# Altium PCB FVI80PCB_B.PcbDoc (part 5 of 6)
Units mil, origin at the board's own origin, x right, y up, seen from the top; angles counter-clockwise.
Board outline 3540 x 3115 mil, 12 copper layers (Top Layer, Int1(GND), Int2(Signal), Int3(GND), Int4(Signal), Int5 (GND&PW), Int6 (GND&PW), Int7(Signal), Int8(GND), Int9(Signal), Int10(GND), Bottom Layer), stack 77.136 mil thick; 488 components, 321 nets, 1809 pads, 882 vias.
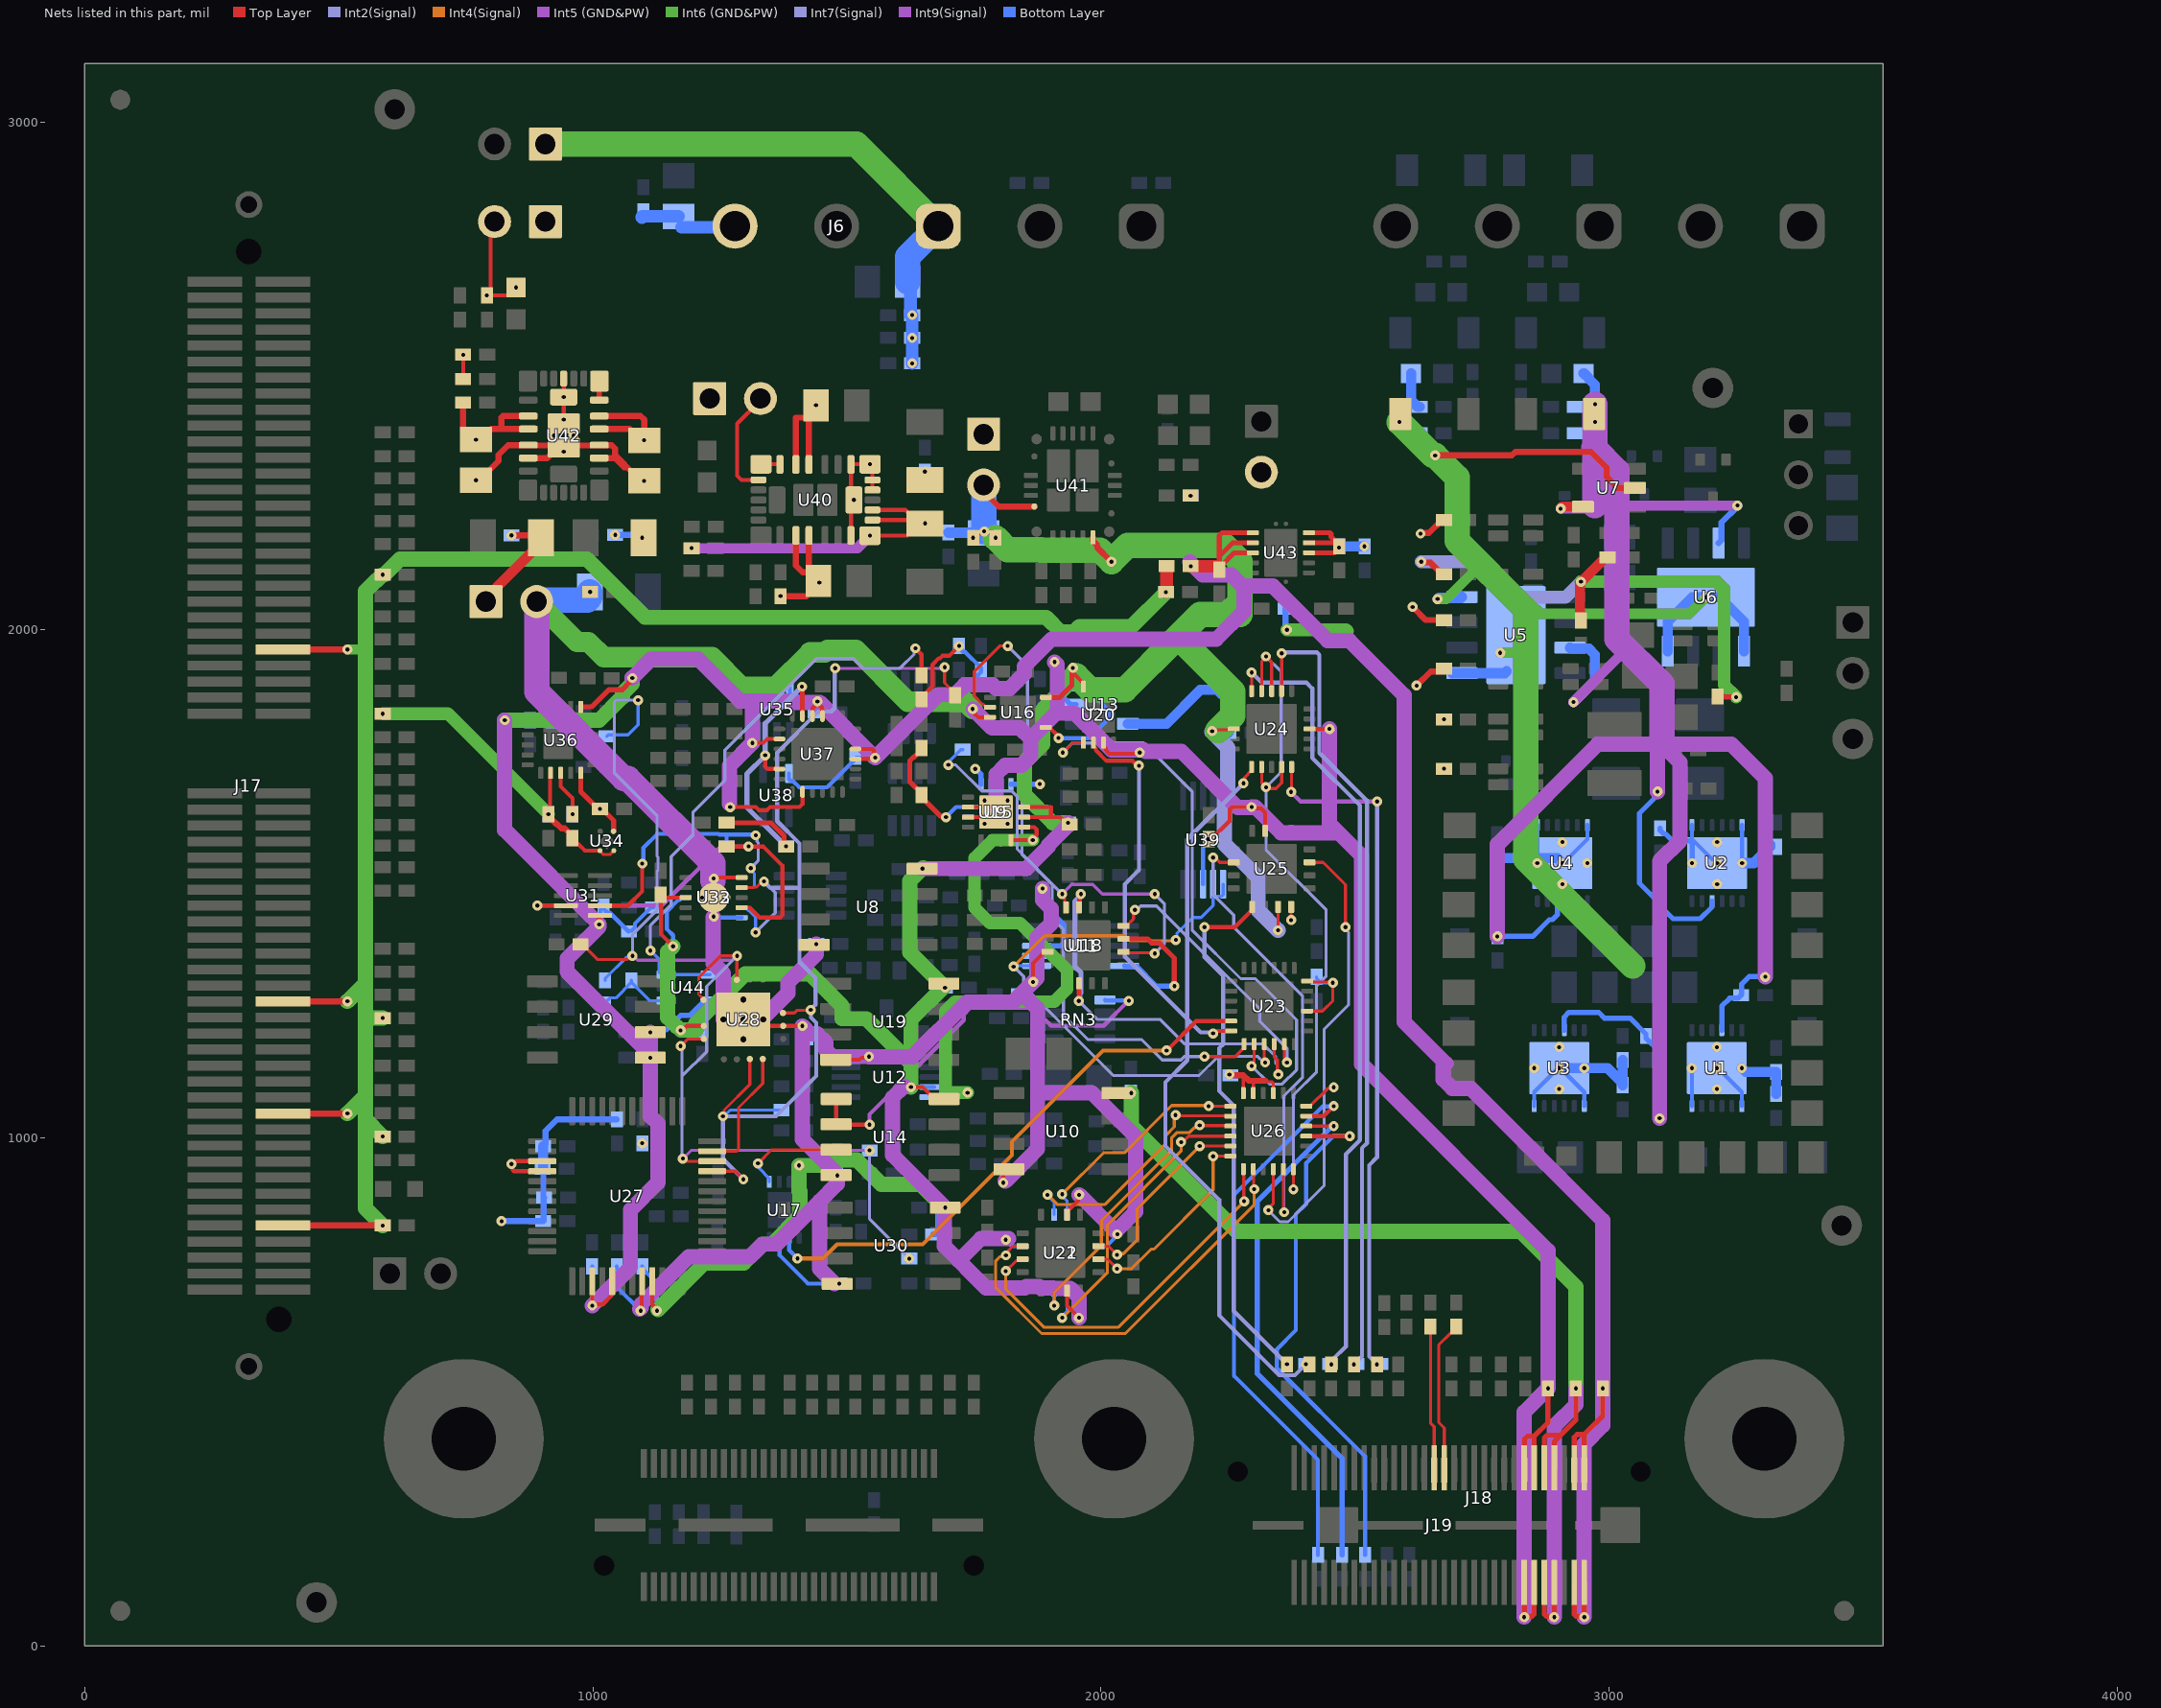
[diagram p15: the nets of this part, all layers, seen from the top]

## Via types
v1: diameter 19.68, hole 7.87, Top Layer to Bottom Layer, tented both sides, 834 vias
v2: diameter 19.68, hole 7.87, Top Layer to Bottom Layer, 39 vias
v3: diameter 23.62, hole 11.81, Top Layer to Bottom Layer, tented both sides, 5 vias
v4: diameter 19.68, hole 7.87, Top Layer to Bottom Layer, tented bottom, 4 vias

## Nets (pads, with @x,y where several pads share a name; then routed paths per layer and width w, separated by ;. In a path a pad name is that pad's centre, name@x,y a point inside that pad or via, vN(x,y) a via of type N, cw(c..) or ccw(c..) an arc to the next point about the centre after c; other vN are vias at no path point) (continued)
NetR200_1: R200.1 R204.1 U24.20 | length 1347.8
  Top Layer w6: v1(2374.57,1681.17) 2375.06,1681.66 2375.06,1729.89 U24.20@2375.56,1730.38
  Int2(Signal) w8: v1(2543.52,554.34) 2528,569.86 2528,946.38 2543.84,962.22 v1(2543.84,1662.52)
  Int9(Signal) w8: v1(2374.57,1681.17) 2393.22,1662.52 v1(2543.84,1662.52)
NetR201_2: R201.2 U26.15 | length 1060
  Top Layer w8: U26.15@2404.51,1003.71 2439.34,1003.71 2439.5,1003.55 2466.52,1003.55 2466.68,1003.71 v1(2489.73,1003.71)
  Bottom Layer w8: v1(2489.73,1003.71) 2489.57,1003.55 2457.07,1003.55 2404,950.48 2404,870 2384,850 2384,621.66 2346.5,584.16 2346.5,546.78 2520,373.28 R201.2@2520,179.27
NetR202_1: R202.1 R204.2 U24.7 | length 1597.6
  Top Layer w6: U24.7@2355.87,1879.99 v1(2355.87,1954)
  Int2(Signal) w8: v1(2355.87,1954) 2357.87,1956 2425.47,1956 2430.16,1951.31 2430.16,1757.89 2524,1664.05 2524,990.12 2514,980.12 2514,570.2 v1(2498.15,554.34)
NetR203_2: R203.2 U26.16 | length 1030.9
  Top Layer w6: U26.16@2404.51,1023.4 v1(2458.3,1023.4)
  Bottom Layer w10: v1(2458.3,1023.4) 2455.7,1023.4 2308,875.69 2308,536 2475,369 R203.2@2475,179.27
NetR205_1: R205.1 R208.1 U24.10 | length 1561.6
  Top Layer w6: U24.10@2296.82,1879.99 v1(2296.82,1916.36)
  Int2(Signal) w8: v1(2296.82,1916.36) 2316.66,1896.52 2404.64,1896.52 2416.16,1885 2416.16,1748.26 2510,1654.41 2510,995.92 2482.41,968.33 2482.41,589.62 2455.7,562.91 2455.7,556.58 v1(2453.46,554.34)
NetR206_2: R206.2 U26.17 | length 1107.5
  Top Layer w8: U26.17@2404.51,1043.08 2438.61,1043.08 v1(2458.3,1062.77)
  Bottom Layer w8: R206.2@2427.38,179.27 2427.38,366.62 2262.22,531.78 2262.22,887.84 2436.46,1062.07 2457.61,1062.07 v1(2458.3,1062.77)
NetR207_1: R207.1 R208.2 U24.16 | length 1422.3
  Top Layer w6: v1(2280.68,1698.42) 2283.3,1701.04 2283.3,1709.98 2296.82,1723.49 U24.16@2296.82,1730.38
  Int2(Signal) w8: v1(2280.68,1698.42) 2170,1587.74 2170,1152.75 2127.16,1109.91 2127.16,984.27 2233.01,878.43 2233.01,650.92 2350.93,533 2381.76,533 v1(2403.76,555)
NetR209_1: R209.1 U25.9 | length 1047.8
  Top Layer w8: v1(2203.87,1415.13) 2263.83,1415.13 2297.8,1449.1 U25.9@2297.8,1455.01
  Int2(Signal) w8: v1(2203.87,1415.13) 2203.87,1356.32 2240.84,1319.35 2240.84,1184.78 2233.06,1177 2233.06,1092.52 2261.38,1064.2 2261.38,659.96 v1(2366.34,555)
NetR232_2: R232.2 R234.1 U44.1 | length 158.9
  Bottom Layer w6: R232.2@1024.47,1262.96 1024.47,1266.89 1033.28,1275.7 1045.44,1275.7 R234.1@1076,1306.26 ; R234.1@1076,1310.2 R234.1@1076,1306.26 ; U44.1@1144.34,1270.41 1111.86,1270.41 R234.1@1076,1306.26
NetR233_1: R233.1 U44.3 U44.4 | length 1144.5
  Top Layer w8: v1(1635,1964) 1646.8,1952.2 R233.1@1646.8,1910.84
  Int2(Signal) w6: v1(1113.36,1368.84) 1113.36,1418.58 1154.24,1459.46 1154.24,1553.9 1197.35,1597.01 1197.35,1641.59 1259.97,1704.21 1259.97,1763.37 1440.44,1943.84 1512.93,1943.84 1532.16,1924.62 1604.65,1924.62 1632.38,1952.35 1632.38,1961.38 v1(1635,1964)
  Bottom Layer w6: v1(1113.36,1368.84) 1130.6,1351.6 1130.6,1326.47 1135.48,1321.59 U44.4@1230.95,1321.59
NetRN3_1: RN3.1 U14.1 U14.2 | length 822.7
  Top Layer w8: U14.1@1478.95,1076.72 U14.2@1478.95,1026.72 1479.24,1026.43 1544.53,1026.43 v1(1544.81,1026.14)
  Int9(Signal) w8: v1(1544.81,1026.14) 1544.81,1046.68 1730.16,1232.02 1730.16,1243.22 1742.99,1256.05 1862.62,1256.05 1886.67,1232 1891.03,1232 1902.03,1221 2005.59,1221 2054.61,1270.02 v1(2055.12,1270.02)
  Bottom Layer w8: RN3.1@2008.19,1271.76 2009.06,1270.89 2054.25,1270.89 v1(2055.12,1270.02)
NetU11_6: U11.6 U11.7 U23.15 U39.6 U39.7 | length 1258.4
  Top Layer w6: U23.15@2321.44,1184.96 2321.44,1150.48 v1(2323.39,1148.53)
  Int4(Signal) w6: v1(1828.34,1337.43) 1888.94,1398.03 2046.86,1398.03 2056.5,1388.4 2146.08,1388.4 v1(2147.68,1390)
  Int7(Signal) w6: v1(1828.34,1337.43) 1847.91,1317.85 1847.91,1299.53 2024.53,1122.91 2193.08,1122.91 2230.76,1160.6 2308.81,1160.6 2320.88,1148.53 v1(2323.39,1148.53)
  Bottom Layer w6: v1(1828.34,1337.43) 1829.75,1338.83 U11.6@1873.59,1338.83 U11.7@1873.59,1358.52 ; v1(2147.68,1390) 2149.59,1391.91 2149.59,1402.74 2180.83,1433.98 2197.03,1433.98 2221,1457.94 U39.7@2221,1476.24 ; U39.7@2221,1499.83 U39.7@2221,1476.24 ; U39.6@2240.68,1499.83 2240.68,1479.14 2237.78,1476.24 U39.7@2221,1476.24
NetU13_3: U13.3 U16.1 | length 243.8
  Top Layer w8: U16.1@1891.9,1808.33 1898.79,1808.33 1914.36,1792.76 1914.36,1789.48 v1(1916.6,1787.24)
  Bottom Layer w8: v1(1916.6,1787.24) 1977.1,1787.24 2015.05,1825.19 2015.05,1841.63 1994.56,1862.11 1988.95,1862.11 1964.06,1887 U13.3@1956,1887
NetU14_3: U14.3 U17.1 | length 209.8
  Top Layer w6: v1(1325,950) 1351.72,976.72 U14.3@1478.95,976.72
  Bottom Layer w6: v1@1327,950 1327.62,949.38 1327.62,940.06 1347.22,920.46 U17.1@1347.22,913.57
NetU16_6: U16.6 U23.13 | length 1365.6
  Top Layer w6: U16.6@1781.67,1847.7 1774.78,1847.7 1769.01,1853.47 1767.28,1853.47 1750.88,1869.87 1750.88,1918.58 1800.93,1968.62 v1(1816.63,1968.62) ; v1(2203.87,1160.36) 2264.55,1160.36 2280.34,1176.15 2280.34,1183.24 U23.13@2282.07,1184.96
  Int7(Signal) w6: v1(1816.63,1968.62) 1855.63,1929.62 1855.63,1762.37 1845,1751.74 1845,1557.74 1904.09,1498.65 1904.09,1432.68 1926.55,1410.22 1926.55,1241.81 1974.49,1193.86 2080.54,1193.86 2120.9,1153.51 2157.52,1153.51 2164.37,1160.36 v1(2203.87,1160.36)
NetU17_6: U17.6 U23.11 | length 1109.9
  Top Layer w8: v1(2129.53,1172.35) 2187.42,1230.24 U23.11@2256.48,1230.24
  Int4(Signal) w8: v1(1402.9,762.89) 1453,762.89 1480.78,790.67 1649.5,790.67 1824.98,966.15 1824.98,992.7 2004.27,1172 2129.18,1172 v1(2129.53,1172.35)
  Bottom Layer w8: U17.6@1386.59,803.34 1386.59,779.2 v1(1402.9,762.89)
NetU18_6: U18.6 U18.15 U23.16 | length 818.1
  Top Layer w6: U23.16@2341.12,1184.96 2341.12,1160.34 2347.5,1153.96 2347.5,1126.89 v1(2349.39,1125)
  Top Layer w10: v1(1956.51,1269.85) 1957.01,1270.34 U18.6@1957.01,1304.38 ; U18.15@1957.01,1453.99 1957.91,1454.9 1957.91,1474.73 1960.75,1477.57 v1(1960.75,1480.19)
  Int2(Signal) w10: v1(1956.51,1269.85) 1958.37,1271.7 1958.37,1283.37 1960.75,1285.75 1960.75,1325.7 1948.96,1337.49 1948.96,1465.78 1960.75,1477.57 v1(1960.75,1480.19)
  Int7(Signal) w6: v1(1956.51,1269.85) 1992.81,1233.55 2116.51,1233.55 2165.09,1184.97 2319.32,1184.97 2344.19,1160.1 2344.19,1146.84 2347.19,1143.84 2347.19,1127.2 v1(2349.39,1125)
NetU18_12: U18.12 U23.17 | length 543.4
  Top Layer w6: U18.12@2044.61,1417.57 2050.51,1417.57 2064.38,1431.44 2064.38,1446.45 v1(2067,1449.07) ; U23.17@2360.81,1184.96 2360.81,1157.77 2366.34,1152.23 v1(2366.34,1148.53)
  Int7(Signal) w6: v1(2067,1449.07) 2070.7,1449.07 2078.33,1456.7 2109.84,1456.7 2312.44,1254.1 2312.44,1230.12 2366.34,1176.21 v1(2366.34,1148.53)
NetU20_5: U20.5 U23.14 | length 1159.8
  Top Layer w6: v1(1925.32,1758.84) 1944.77,1778.29 U20.5@1965.68,1778.29 ; v1(2296.82,1141.76) 2296.82,1145.46 2301.75,1150.4 U23.14@2301.75,1184.96
  Int7(Signal) w6: v1(1925.32,1758.84) 1943.97,1777.49 2084.16,1777.49 2179.7,1681.96 2179.7,1409.26 2275.23,1313.73 2303.96,1313.73 2385.19,1232.51 2385.19,1134.15 2357.19,1106.16 2332.41,1106.16 v1(2296.82,1141.76)
NetU20_6: U20.6 U23.12 | length 775.6
  Top Layer w8: U20.6@1985.36,1778.29 1985.36,1771.4 1990.12,1766.64 1990.12,1763.38 2011.02,1742.48 2062.36,1742.48 2071.84,1733 v1(2075,1733) ; v1(2221,1205.81) 2224.16,1205.81 2228.9,1210.55 U23.12@2256.48,1210.55
  Int7(Signal) w8: v1(2075,1733) 2075,1527.61 2047.16,1499.77 2047.16,1357.27 2196.38,1208.05 2218.76,1208.05 v1(2221,1205.81)
NetU21_6: U21.6 U26.4 | length 602.2
  Top Layer w6: v1(2158,992) 2161.23,992 2172.94,1003.71 U26.4@2254.9,1003.71
  Int4(Signal) w6: v1(1923.78,646) 2012.93,735.16 2012.93,828.93 2158,974 v1(2158,992)
  Bottom Layer w6: v1(1923.78,646) 1923.78,649.7 1933.43,659.36 U21.6@1933.43,699.41
NetU21_7: U21.7 U26.3 | length 581.9
  Top Layer w6: v1(2194.5,1025.08) 2195.34,1024.24 2254.06,1024.24 U26.3@2254.9,1023.4
  Int4(Signal) w6: v1(1908.3,670) 1908.3,695.86 2000.93,788.49 2000.93,836.93 2139.16,975.16 2139.16,999.81 2150.2,1010.84 2174.84,1010.84 2184.47,1020.47 2186.19,1020.47 2190.8,1025.08 v1(2194.5,1025.08)
  Bottom Layer w6: U21.7@1907.84,699.41 1908.07,699.17 1908.07,670.23 v1(1908.3,670)
NetU21_14: U21.14 U26.2 | length 507.3
  Top Layer w6: v1(2147,1045) 2148.08,1043.92 2254.06,1043.92 U26.2@2254.9,1043.08
  Int4(Signal) w6: v1(1895.04,888.07) 1913.88,869.22 2008.22,869.22 2127.16,988.16 2127.16,1004.78 2144.38,1022 2144.38,1042.38 v1(2147,1045)
  Bottom Layer w6: v1(1895.04,888.07) 1895.04,887.01 1907.84,874.21 U21.14@1907.84,849.01
NetU21_15: U21.15 U26.1 | length 448.2
  Top Layer w6: v1(2212.13,1062.77) U26.1@2254.9,1062.77
  Int4(Signal) w6: v1(1923.78,889.33) 2005.18,970.73 2046.09,970.73 2139.2,1063.84 2211.05,1063.84 v1(2212.13,1062.77)
  Bottom Layer w6: v1(1923.78,889.33) 1923.78,885.62 1933.43,875.97 U21.15@1933.43,849.01
NetU22_6: U22.6 U26.8 | length 841.8
  Top Layer w6: v1(1813,769) 1815.62,771.62 1815.62,775.89 1826.73,787.01 U22.6@1845.83,787.01 ; U26.8@2300.18,938.75 2300.96,937.96 2300.96,900.09 v1(2301.75,899.31)
  Int4(Signal) w6: v1(1813,769) 1810.38,766.38 1801.38,766.38 1793,758 1793,705.59 1883.43,615.16 2048.32,615.16 2301.75,868.59 v1(2301.75,899.31)
NetU22_7: U22.7 U26.7 | length 745.1
  Top Layer w6: v1(1812.94,738) 1833.45,758.51 1842.92,758.51 U22.7@1845.83,761.41 ; U26.7@2280.49,938.75 2281.28,937.96 2281.28,876.34 v1(2282.07,875.55)
  Int4(Signal) w6: v1(1812.94,738) 1812.94,702.62 1888.4,627.16 2033.67,627.16 v1(2282.07,875.55)
NetU22_14: U22.14 U26.6 | length 397.8
  Top Layer w6: U22.14@1995.44,761.41 2013.04,761.41 v1(2031.78,742.68) ; v1(2221,964.01) 2221.16,964.18 2254.74,964.18 U26.6@2254.9,964.34
  Int4(Signal) w6: v1(2031.78,742.68) 2060.63,742.68 2099.26,781.31 2104.51,781.31 2221,897.8 v1(2221,964.01)
NetU22_15: U22.15 U26.5 | length 391.1
  Top Layer w6: U22.15@1995.44,787.01 2014.89,787.01 v1(2031.78,770.12) ; v1(2194.5,984.03) U26.5@2254.9,984.03
  Int4(Signal) w6: v1(2031.78,770.12) 2033.93,772.27 2044.27,772.27 2071.77,799.77 2071.77,861.29 v1(2194.5,984.03)
NetU27_11: U27.11 U28.8 | length 251.1
  Top Layer w6: U27.11@1235.2,973.98 1283.39,973.98 1286.9,977.49 1286.9,1059.73 1334.74,1107.56 U28.8@1334.74,1155.62
NetU40_20: U40.20 U40.21 | length 37.6
  Top Layer w8: U40.21@1330.97,2326.36 1367.94,2326.36 U40.20@1368.37,2325.92
NetU42_20: U42.20 U42.21 | length 37.6
  Top Layer w10: U42.20@1012.67,2452.68 1012.89,2452.89 1012.89,2489.86 U42.21@1013.1,2490.08
REF_2.5: C54.1 C55.2 R121.2 U37.11 U37.17 | length 648.3
  Top Layer w8: v1(1339.3,1753.28) 1339.3,1731.13 1343.99,1726.44 U37.17@1367.46,1726.44
  Top Layer w10: R121.2@1263.44,1620.51 1350.72,1620.51 1376.4,1594.83 1376.4,1578.07 v1(1380.59,1573.88) ; v1(1411.77,1888.53) 1412.46,1887.83 1412.46,1831.05 U37.11@1412.74,1830.77
  Int2(Signal) w10: v1(1380.59,1573.88) 1303.28,1651.18 1303.28,1716.77 1339.3,1752.79 1339.3,1816.06 v1(1411.77,1888.53)
REF_4: C65.1 C72.2 R94.1 R233.2 | length 281.3
  Top Layer w8: R233.2@1646.8,1863.6 1646.8,1867.54 1668.61,1889.35 1668.61,1931.96 1680.81,1944.16 1683.22,1944.16 1688.24,1949.17 1701.55,1949.17 v1(1721,1968.62)
  Bottom Layer w8: R94.1@1721,1870.62 1721,1874.56 1756.07,1909.63 1756.45,1909.63 1764.26,1917.44 C65.1@1764.26,1921.38 1764.26,1925.32 1732.71,1956.87 1728.81,1956.87 1721,1964.68 v1(1721,1968.62)
REF_4096: R68.2 R120.2 R124.2 R138.2 R232.1 U27.10 U28.1 U28.4 U28.15 | length 2557
  Top Layer w6: R124.2@976.09,1381.03 980.03,1381.03 1009.9,1351.16 1067.1,1351.16 1074.46,1358.52 v1(1078.16,1358.52) ; v1(1173,1181) 1186.99,1194.99 U28.4@1218.6,1194.99 ; v1(1177.33,959.41) 1178.88,959.41 1184,954.29 U27.10@1235.2,954.29 ; U28.1@1217.89,1271.76 1217.89,1273.49 1208.62,1282.77 1208.62,1315.84 1251.3,1358.52 v1(1284.15,1358.52) 1283.56,1357.93 U28.15@1283.56,1311.13
  Int2(Signal) w6: v1(1078.16,1358.52) 1078.16,1400.35 1126.18,1448.37 1126.18,1525.34 1128.25,1527.41 1128.25,1552.96 1126.18,1555.03 1126.18,1634.64 1042.68,1718.14 1042.68,1858.49 1046.19,1862 v1(1089,1862) ; v1(1173,1181) 1175.38,1178.62 1175.38,1121.25 ; v1(1177.33,959.41) 1175.38,961.36 1175.38,1121.25 ; v1(1284.15,1358.52) 1224.17,1298.54 1224.17,1170.05 1175.38,1121.25 ; v1(1544.81,975.49) 1544.81,840.45 v1(1622.8,762.47)
  Int9(Signal) w6: v1(1078.16,1358.52) 1080,1358.52 1088.52,1350 1273.79,1350 1282.31,1358.52 v1(1284.15,1358.52) ; v1(1089,1862) v1@1090.03,1863.03 ; v1(1177.33,959.41) 1193.4,975.49 v1(1544.81,975.49)
  Bottom Layer w6: R232.1@1024.47,1310.2 1024.47,1314.14 1066.23,1355.9 1075.54,1355.9 v1(1078.16,1358.52) ; R138.2@1027.47,1790.44 1030.54,1793.5 1069.32,1793.5 1089,1813.18 v1(1089,1862)
REF_4096N: R75.2 R99.1 U27.9 U28.7 U28.11 U32.4 U33.4 | length 2216.2
  Top Layer w6: U27.9@1235.2,934.61 1280.65,934.61 1296.35,918.91 v1(1296.35,918.63) ; v1(1256.28,1042.72) 1258.59,1045.02 1258.59,1055.06 1309.15,1105.62 U28.7@1309.15,1155.62 ; U33.4@1293.04,1492.94 1316.49,1492.94 1317.32,1493.77 1321.83,1493.77 1333.17,1505.11 v1(1336.87,1505.11) ; U28.11@1374.11,1246.17 1396.68,1246.17 1401.75,1251.24 1428.24,1251.24 v1(1429,1252) ; v1(1692.5,1926.62) 1692.5,1896.06 1715,1873.56 R99.1@1715,1873
  Int2(Signal) w6: v1(1320.51,1404.78) 1359.15,1443.4 1359.15,1482.83 1349.52,1492.46
  Int2(Signal) w8: v1(1296.35,918.63) 1256.28,958.7 v1(1256.28,1042.72) 1360.54,1042.72 1439.91,1122.09 1439.91,1226.74 1429.27,1237.38 v1@1429.27,1251.73 ; v1(1336.87,1505.11) 1349.52,1492.46 1406.76,1492.46 ; v1@1429,1253.11 1438.25,1262.36 1438.25,1315.6 1406.76,1347.09 1406.76,1492.46 ; v1(1477,1925) 1476.33,1924.33 1476.33,1846.89 1468.92,1839.48 1443.92,1839.48 1363,1758.56 1363,1623.62 1406.76,1579.86 1406.76,1492.46
  Int9(Signal) w6: v1(1477,1925) 1477.38,1924.62 1690.5,1924.62 v1(1692.5,1926.62)
  Bottom Layer w6: v1(1256.28,1042.72) 1258.36,1042.72 1270.65,1055 R75.2@1371.16,1055 ; U32.4@1293.04,1453.57 1294.77,1451.85 1301.85,1451.85 1306.09,1447.61 1307.42,1447.61 1320.51,1434.52 v1(1320.51,1404.78)
REF_SEL: R141.1 R142.2 U36.20 | length 90.9
  Top Layer w8: U36.20@936.8,1718.68 936.8,1692.14 960.07,1668.87 v1(960.07,1637.47)
Signal_H_L_Select: U24.8 U24.9 U24.17 U24.19 U26.12 | length 1444.5
  Top Layer w6: U24.17@2316.5,1730.38 2316.5,1698.86 v1(2325,1690.36) 2327.37,1687.99 2344.47,1687.99 2355.87,1699.39 U24.19@2355.87,1730.38 ; U24.9@2316.5,1879.99 2316.5,1937.64 2325,1946.14 v1(2325,1948) ; v1@2324,1949 v1(2325,1948) ; U24.8@2336.19,1879.99 2336.19,1936.81 v1(2325,1948) ; v1@2378.92,899.31 U26.12@2378.92,938.75
  Int7(Signal) w6: v1@2325,1690 2325,1567.64 2443.39,1449.25 2443.39,1318.99 2424.55,1300.14 2424.55,1130.2 2379,1084.65 v1(2379,899) ; v1(2325,1948) 2355.03,1917.97 2355.03,1720.38 2328,1693.36 v1@2328,1690
Switch_11_LV: U25.15 U26.10 | length 937.4
  Top Layer w6: v1(2329.7,857.8) 2329.7,861.5 2339.55,871.34 U26.10@2339.55,938.75 ; U25.15@2410.99,1542.6 2437.59,1542.6 2481.46,1498.73 v1(2481.46,1415.13)
  Int7(Signal) w6: v1(2329.7,857.8) 2352.34,835.16 2368.61,835.16 2439.46,906 2439.46,1213.93 2487.63,1262.1 2487.63,1405.26 2481.46,1411.43 v1(2481.46,1415.13)
Switch_12_LV: U25.6 U26.11 | length 916.3
  Top Layer w6: v1(2221,1552) 2224.7,1552 2234.1,1542.6 U25.6@2261.38,1542.6 ; U26.11@2359.23,938.75 2359.23,855.58 v1(2360.81,854)
  Int7(Signal) w6: v1(2221,1552) 2221,1479.43 2261.38,1439.05 2261.38,1415.13 2397.19,1279.32 2397.19,1119.8 2360.16,1082.78 2360.16,854.65 v1(2360.81,854)
VCC_LV_ext: C1.2 C2.2 C5.2 C6.2 C11.1 C12.1 C13.1 R211.2 U1.10 U2.10 U3.10 U4.10 U5.7 U6.7 U7.5 | length 4809.2
  Top Layer w20: v1@2907.6,2242.6 U7.5@2948.82,2242.6
  Int5 (GND&PW) w20: v1(2905,2239) 2963,2239 ; v1(2930.33,1858) 3029,1956.67 ; 3015.5,2245 v1(3253,2245)
  Int5 (GND&PW) w30: v1(2780.34,1396.9) 2780.34,1577.77 2977.57,1775 3241.16,1775 3307.62,1708.53 v1(3307.62,1317.27) ; v1(3095.59,1682) 3095.59,1766.59 ; v1(3099.82,1038.75) 3099.82,1545.13 3139.99,1585.3 3139.99,1739.01 3104,1775
  Int5 (GND&PW) w50: 2970,2359 2972.52,2356.48 ; 2972.52,2245 2972.52,2356.48 ; 2972.52,2359 v1(2972.52,2409.48) v1(2972.52,2444.25) ; 3104,1775 3104,1894 3015.5,1982.5 3015.5,2245 3015.5,2313.5 2972.52,2356.48
  Bottom Layer w10: v1(2780.34,1396.9) 2849.74,1396.9 2882.59,1429.75 2888.74,1429.75 2898.54,1439.55 U4.10@2898.54,1466.37 ; U3.10@2912.1,1212.42 2912.1,1238.28 2921.05,1247.24 2979.76,1247.24 2991,1236 3041.56,1236 3073,1204.56 C5.2@3073,1200.62 3073,1196.69 3099.82,1169.86 v1(3099.82,1038.75) ; v1(3095.59,1682) 3095.59,1674.67 3060,1639.07 3060,1501.59 3100.81,1460.78 C2.2@3100.81,1456.84 3100.81,1452.9 3107.62,1446.09 3111.56,1446.09 3126.09,1431.55 3179.66,1431.55 3202.95,1454.84 3202.95,1466.29 U2.10@3203.02,1466.37 ; U1.10@3222.32,1212.42 3222.32,1259.76 3237.79,1275.24 3254.2,1275.24 3261.34,1282.38 3261.34,1303.07 3276.42,1318.15 3306.74,1318.15 v1(3307.62,1317.27)
  Bottom Layer w12: U6.7@3216,2171 3221.81,2176.81 3221.81,2211.81 3253,2243 v1(3253,2245)
  Bottom Layer w20: U5.7@2923.35,1965 2925.16,1963.19 2960.8,1963.19 2972.52,1951.47 2972.52,1900.19 v1(2930.33,1858) ; R211.2@2950.17,2505 2951.15,2505 2959.86,2496.3 2959.86,2495.32 2972.52,2482.65 v1(2972.52,2444.25)
VCLH+: R128.1 U31.2 U32.2 | length 577.4
  Top Layer w8: U31.2@1013.83,1457.51 1069.43,1457.51 1097.41,1485.48 v1(1097.41,1540.19)
  Int2(Signal) w6: v1(1311.02,1531.22) 1325.36,1545.56 1325.36,1581.68 1323.29,1583.75 1323.29,1589.5 1320.67,1592.12 v1(1320.67,1595.83)
  Bottom Layer w6: U32.2@1293.04,1492.94 1314.52,1492.94 1318.03,1496.46 1318.03,1520.51 1311.02,1527.52 v1(1311.02,1531.22)
  Bottom Layer w8: v1(1097.41,1540.19) 1099.64,1542.42 1099.64,1571.42 1127.08,1598.86 1247.77,1598.86 1249.28,1597.35 1260.26,1597.35 ; R128.1@1263.44,1573.54 1263.44,1594.17 1260.26,1597.35 ; v1(1320.67,1595.83) 1319.15,1597.35 1260.26,1597.35
VCLL+: R129.1 U31.9 U33.2 | length 833.1
  Top Layer w8: v1(890.97,1457.51) U31.9@946.9,1457.51 ; R129.1@1263.44,1573.54 1263.61,1573.71 1306.34,1573.71 v1(1306.51,1573.88) 1306.85,1573.54 1336.05,1573.54 1373.13,1536.46 1373.13,1438.57 1368.44,1433.89 1328.47,1433.89 1309.51,1452.85 1293.77,1452.85 U33.2@1293.04,1453.57
  Int9(Signal) w8: v1(890.97,1457.51) 1135.51,1457.51 1251.53,1573.54 1306.17,1573.54 v1(1306.51,1573.88)
VDD_1V8: C79.1 C80.2 U34.1 U36.22 | length 146.5
  Top Layer w10: U36.22@976.17,1718.68 976.17,1681.96 1010.34,1647.79 v1(1014.28,1647.79) 1018.21,1647.79 1040.94,1625.07 1040.94,1603.89 U34.1@1040.75,1603.7
VDD_3V3: C43.2 C44.2 C70.1 C71.2 C77.1 C78.2 C128.1 C129.1 C130.1 R22.1 R23.1 R30.1 R33.1 R34.1 R35.1 R36.1 R37.1 R38.1 R115.2 R116.2 R117.2 R118.2 R135.2 R141.2 R155.1 U9.1 U9.4 U12.10 U15.4 U15.5 U23.21 U23.24 U25.12 U26.18 U26.21 U26.23 U26.24 U27.27 U27.28 U34.3 U34.4 U36.19 U43.8 U43.9 U43.10 | length 4588.6
  Top Layer w6: U34.3@1014.15,1565.74 1014.15,1564.69 1021,1557.83 1033.46,1557.83 U34.4@1041.36,1565.74 ; v1@2254.66,1125 v1@2256.13,1123.53 ; 2280.45,1123.53 2280.49,1123.49 U26.24@2280.49,1088.36 ; U26.23@2300.18,1088.36 2300.18,1110.41 2302.32,1112.56 ; 2323.76,1112.56 2325.32,1111 2336.03,1111 2339.55,1107.49 U26.21@2339.55,1088.36 ; v1(2374.57,1429.1) U25.12@2374.57,1455.01 ; U26.18@2404.51,1062.77 2411.59,1062.77 2446.21,1097.38 2455.68,1097.38 v1(2458.3,1100) ; U23.21@2406.08,1249.92 2436.36,1249.92 2456.6,1270.16 v1(2456.6,1305.55) 2454.88,1307.26 2407.8,1307.26 U23.24@2406.08,1308.98
  Top Layer w8: v1(840,948.83) 843.16,948.83 848.62,954.29 U27.27@900.56,954.29 ; v1@842.24,946.6 842.24,937.06 844.69,934.61 U27.28@900.56,934.61 ; C77.1@912.78,1633.59 916.19,1637 916.19,1717.76 U36.19@917.11,1718.68 ; R141.2@960.07,1590.22 960.07,1586.28 967.88,1578.47 971.82,1578.47 984.56,1565.74 U34.3@1014.15,1565.74 ; U15.4@1823.32,1586.4 v1(1865.86,1586.4) 1865.86,1589.57 1873.57,1597.27 1873.57,1607.31 1868.89,1611.99 U15.5@1848.91,1611.99
  Top Layer w10: U43.8@2409.43,2152.03 2460.27,2152.03 2468.79,2160.55 v1(2468.79,2162.52) C129.1@2468.79,2164.49 2468.79,2168.43 2453,2184.22 2453,2188.87 2450.47,2191.4 U43.10@2409.43,2191.4 ; U43.9@2409.43,2171.72 C129.1@2461.98,2171.72 ; R22.1@3213.64,1869.11 3214.75,1868 v1(3250.5,1868)
  Top Layer w12: C77.1@912.78,1633.59 928.34,1618.03 929.56,1618.03 937.87,1609.72 944.51,1609.72 960.07,1594.16 R141.2@960.07,1590.22 ; v1@2256.13,1123.53 2280.45,1123.53 ; 2280.49,1123.49 2291.42,1112.56 2302.32,1112.56 2323.76,1112.56 ; v1(2613.5,2045.5) 2639.39,2019.61 R36.1@2675.52,2019.61 ; v1(2621.5,1890.5) 2649.42,1918.42 2669.7,1918.42 R35.1@2675.52,1924.23 ; v1(2629.16,2189.55) 2630.63,2191.02 2645.79,2191.02 2671.58,2216.81 R38.1@2675.52,2216.81 ; v1(2630.61,2134.51) 2632.08,2133.04 2648.46,2133.04 2671.58,2109.92 R37.1@2675.52,2109.92
  Top Layer w20: R30.1@2945,2018.62 2943.19,2020.43 2943.19,2093.22 v1(2945,2095.03) 2945.47,2095.03 2993.44,2143 R23.1@2997.38,2143
  Int6 (GND&PW) w25: v1(586.38,1835.3) 715.01,1835.3 v1(912.78,1637.52) ; v1(1737.69,1089.29) 1694.29,1089.29 1694.29,1249.53 1713.16,1268.4 1908.49,1268.4 1933.34,1293.26 1933.34,1330.8 1840.88,1423.27 1781.4,1423.27 1751.34,1453.33 1751.34,1551.01 1786.73,1586.4 v1(1865.86,1586.4) ; v1(2366.34,2000.5) 2483.04,2000.5 2485.61,1997.92 ; v1(2945,2095.03) 3212.01,2095.03 3226.65,2080.38 3226.65,1891.85 v1(3250.5,1868)
  Int7(Signal) w25: v1(2630.61,2134.51) 2738.9,2134.51 2808.71,2064.7 2914.36,2064.7 2944.68,2095.03 v1(2945,2095.03)
  Bottom Layer w6: C44.2@2424.55,1317.27 2424.55,1314.36 2433.36,1305.55 v1(2456.6,1305.55)
  Bottom Layer w8: U12.10@1671.61,1080.63 1725.87,1080.63 1734.52,1089.29 v1(1737.69,1089.29)
  Bottom Layer w10: v1(1752.8,1726.68) 1753.56,1726.68 1764.26,1715.98 U9.1@1764.26,1696.64 ; U9.4@1823.32,1696.64 v1(1880,1696.64)
  Bottom Layer w12: v1(820.32,836.18) R118.2@902.52,836.18 903.19,836.85 903.19,881.89 R116.2@903.86,882.56 902.7,883.72 902.7,938.37 C71.2@901.54,939.53 ; C70.1@902.03,983.18 C70.1@902.52,983.67 906.76,987.91 906.76,1013.75 929.83,1036.82 R115.2@1047.21,1036.82 ; R155.1@2363.74,2042.03 2363.74,2005.18 2366.34,2002.58 v1(2366.34,2000.5)
  Bottom Layer w20: C71.2@901.54,939.53 902.03,940.02 C70.1@902.03,983.18 ; v1(2468.79,2162.52) 2468.79,2162.68 2470.6,2164.49 v1(2518.79,2164.49)
  other v1: 1097.41,989.58 2252.9,1125 2675.52,1726.97 2675.52,1824.08
VDD_5V: C47.1 C48.2 C63.2 C64.2 C75.1 C76.2 C85.2 C89.2 C118.1 C119.1 C131.1 C148.1 FB2.1 J11.2 J18.21 J18.22 J19.57 J19.58 J19.59 J19.60 R125.2 R126.2 U27.39 U27.41 U29.1 U29.2 U31.1 U35.5 U36.7 U37.3 U37.4 U37.9 U37.10 U37.14 U37.20 U38.5 U43.1 U43.2 U43.3 U44.5 | length 8160.8
  Top Layer w8: U27.39@998.98,718.07 v1(998.98,670) 1001.22,672.24 1019.29,672.24 1036.45,689.39 1036.45,716.17 U27.41@1038.35,718.07 ; v1(1270.25,1651.36) 1320.98,1651.36 1326.76,1645.58 1343.2,1645.58 1348.99,1651.36 1406.75,1651.36 1412.74,1657.36 U37.20@1412.74,1681.17 ; v1(1314.16,1777.63) 1314.38,1777.85 1336.01,1777.85 1343.65,1785.5 U37.14@1367.46,1785.5 ; U37.10@1432.42,1830.77 1432.7,1831.05 1432.7,1846.59 v1@1442.27,1856.16 ; v1(1442.27,1859.32) v1@1442.27,1856.16 ; U37.9@1452.11,1830.77 1451.83,1831.05 1451.83,1846.59 v1@1442.27,1856.16 ; U37.3@1517.07,1746.13 1517.35,1746.41 1553.67,1746.41 v1(1555.82,1748.55) 1553.58,1750.79 1553.58,1762.69 1550.46,1765.81 U37.4@1517.07,1765.81
  Top Layer w10: U36.7@976.17,1848.6 976.17,1848.7 976.25,1848.77 998.07,1848.77 1031.92,1882.62 1058.33,1882.62 1065.4,1889.7 1065.4,1890.49 1077.72,1902.81 v1(1077.72,1905.44) ; v1(1012.6,1420.39) 1012.6,1437.55 1012.87,1437.82 U31.1@1013.83,1437.82 ; C131.1@2228.69,2125.65 2235.94,2125.65 2262.32,2152.03 U43.3@2299.19,2152.03 ; C131.1@2233.01,2129.53 2233.01,2185.54 2238.86,2191.4 U43.1@2299.19,2191.4 ; 2237.53,2149.53 2259.72,2171.72 U43.2@2299.19,2171.72 ; J19.57@2931.75,125.21 2931.75,62.73 2935.75,58.72 2949.58,58.72 v1(2951.43,56.87) J19.59@2951.43,125.21 ; J18.21@2931.75,346.27 J19.58@2931.75,350.8 2931.79,350.84 2931.79,410.58 2937.65,416.43 2951.43,416.43 ; J19.60@2951.43,350.8 2951.43,416.43 ; v1(2987.92,507.1) 2987.92,452.92 2951.43,416.43
  Top Layer w25: v1(2176.78,2125.65) C131.1@2228.69,2125.65
  Int5 (GND&PW) w30: v1(826.6,1822.4) 826.6,1606.39 v1(1012.6,1420.39) 1012.6,1416.28 949.38,1353.07 949.38,1327.52 v1@1113.36,1163.54 ; v1(998.98,670) 1074,745.02 1074,858.45 1128.25,912.7 1128.25,1027.91 1113.36,1042.8 v1(1113.36,1158.02) v1@1113.36,1163.54 ; v1(1077.72,1905.44) 1115.74,1943.46 1206.75,1943.46 1290.02,1860.18 1313,1860.18 ; v1(1113.36,1208.02) v1@1113.36,1163.54 ; v1@1269,1658 1269,1732.47 v1(1314.16,1777.63) 1314,1777.79 1314,1860 ; 1314,1860.18 1396.5,1860.18 1399,1857.68 1424.55,1857.68 v1@1442.27,1857.68 ; v1@1446.69,1857.68 v1(1555.82,1748.55) 1680.1,1872.83 1712.56,1872.83 1731.73,1892 1787.07,1892 1794.57,1884.5 1820.12,1884.5 1849.16,1913.54 1849.16,1928.07 1903.09,1982 2227,1982 2282,2037 2282,2083 2256.5,2108.5 2200.5,2108.5 v1@2175,2134 ; 2282,2086.54 2338.78,2086.54 2446.28,1979.04 2489.34,1979.04 2596.84,1871.54 2596.84,1228.78 2678.95,1146.67 2673.58,1141.29 2673.58,1115.74 2691.64,1097.68 2727.94,1097.68 2987.92,837.69 v1(2987.92,507.1) 2987.92,434.12 2951.43,397.63 v1(2951.43,56.87)
  Int6 (GND&PW) w30: v1(826.6,1822.4) 1012.62,1822.4 1058.16,1867.93 1058.16,1874.78 1077.72,1894.34 v1(1077.72,1905.44)
  Bottom Layer w8: v1(998.98,670) C63.2@998.98,747.38 ; v1(1012.6,1420.39) 1014.83,1422.63 1014.83,1449.23 R125.2@1020.85,1455.25 1020.85,1451.31 1028.66,1443.5 1033.5,1443.5 C64.2@1070.27,1406.73 ; C64.2@1074,1408 1076.41,1408 1082.95,1414.54 1082.95,1422.21 1114.31,1453.57 R126.2@1118.25,1453.57 ; U38.5@1386.17,1717.59 1386.17,1706.76 1390.04,1702.89 1393.74,1702.89 1406.54,1690.09 1461.03,1690.09 1518.58,1747.64 1518.58,1748.55 v1(1555.82,1748.55) ; U35.5@1388.05,1886.88 1388.05,1876.05 1391.93,1872.18 1399.88,1872.18 1413.95,1858.11 v1@1441.05,1858.11
  Bottom Layer w10: v1(1113.36,1208.02) 1117.92,1212.58 1144.11,1212.58 1172.71,1241.18 1190.89,1241.18 1220.12,1270.41 U44.5@1230.95,1270.41
  Bottom Layer w12: C89.2@1438.33,1837.66 1440.8,1840.13 1440.8,1857.85 1441.05,1858.11 v1(1442.27,1859.32)
  Bottom Layer w20: v1(826.6,1822.4) C75.1@877.04,1822.4 C76.2@919.51,1822.4
  other v1: 2176.63,2264.33
VDD_5V_C2K: C116.1 C117.1 C144.2 C145.2 C146.2 C147.2 FB2.2 J17.48 J17.84 J17.98 J17.112 | length 3806.1
  Top Layer w12: J17.112@389.93,827.68 v1(586.5,827.68) ; J17.98@389.93,1048.15 v1(517,1048.15) ; J17.84@389.93,1268.62 390.18,1268.87 516.75,1268.87 v1(517,1269.12) ; J17.48@389.93,1961.54 v1(517,1961.54)
  Top Layer w25: v1(2128.19,2074.47) 2128.84,2074.47 2129.53,2075.16 FB2.2@2129.53,2125.65
  Int6 (GND&PW) w20: v1(517,1961.54) 552.88,1961.54
  Int6 (GND&PW) w30: v1(517,1048.15) 552.88,1084.03 ; v1(517,1269.12) 552.88,1305 ; v1(586.38,1236) 555.51,1236 552.88,1233.37 ; v1(586.5,827.68) 552.88,861.3 552.88,1036.48 ; v1(586.5,1002.85) 552.88,1036.48 ; v1(2128.19,2074.47) 2060.72,2007 1957.73,2007 1946.76,1996.03 1921.21,1996.03 1892.23,2025 1103,2025 988.19,2139.81 620.85,2139.81 590,2108.97 v1(586.38,2108.97) 574.98,2097.57 573.6,2097.57 552.88,2076.85 552.88,1961.54 552.88,1305 ; 552.88,1036.48 552.88,1084.03 ; 552.88,1084.03 552.88,1233.37 ; 552.88,1233.37 552.88,1305
VDD_12VN: C29.1 C31.1 C33.1 C34.1 C45.1 C66.1 C67.1 C68.1 C69.1 C123.2 C124.2 C150.1 J13.2 J18.16 J18.17 J19.47 J19.48 J19.49 J19.50 U8.4 U9.14 U9.15 U9.17 U10.4 U11.8 U12.5 U13.2 U14.4 U15.14 U15.15 U15.17 U16.7 U17.7 U18.3 U19.4 U20.7 U21.2 U22.2 U24.3 U25.3 U27.44 U28.10 U28.17 U30.4 U32.5 U32.11 U33.5 U33.11 U39.8 | length 10510.5
  Top Layer w8: v1(1094.06,660) 1095.73,661.67 1095.73,716.4 U27.44@1097.41,718.07 ; v1(1237.92,1510.66) 1239.89,1512.63 U33.5@1293.04,1512.63 ; v3(1335.72,1233.37) 1335.72,1230.36 1345.5,1220.58 U28.10@1374.82,1220.58 v1(1412.74,1220.58) ; U19.4@1478.24,1154.02 1524.97,1154.02 1529.07,1158.12 1541.43,1158.12 v1(1543.66,1160.36) ; U15.15@1738.67,1631.68 1773.32,1631.68 U15.17@1774,1631 ; U15.14@1738.67,1651.36 1739.64,1651.36 1740,1651 1740.36,1651.36 1775.36,1651.36 U15.17@1776,1652 ; v1(1747.68,1844.6) 1749.91,1842.36 1749.91,1837.09 1758.98,1828.02 U16.7@1781.67,1828.02 ; v1(1866.76,1307.34) 1866.76,1344.05 1889.1,1366.39 U18.3@1895,1366.39 ; U22.2@1933.43,849.01 1933.43,854.92 1955.05,876.54 1955.05,885.83 v1(1957.28,888.07) ; U20.7@2005.05,1778.29 2005.05,1771.4 2009.81,1766.64 2009.81,1763.49 2016.82,1756.48 2074.19,1756.48 v1(2076.36,1758.65) ; C45.1@2212.13,1583.72 2253.84,1625.44 2253.84,1646.68 2258.74,1651.57 v1(2296.82,1651.57) 2299.05,1649.34 2314.75,1649.34 2323.39,1640.7 U25.3@2323.39,1604.61 ; v1(2212.13,1588.37) C45.1@2212.13,1592.31 ; U24.3@2410.99,1805.18 v1(2450,1805.18)
  Top Layer w10: C34.1@1646.8,1767.81 1646.8,1763.87 1632.64,1749.71 1631.06,1749.71 1623.99,1742.63 1623.99,1701.83 1646.8,1679.02 C33.1@1646.8,1675.09 1646.8,1671.15 1684.42,1633.53 1693.38,1633.53 v1(1695.24,1631.68) ; v1@1808,913 1808,931.55 1814.81,938.36 U10.4@1819.18,938.36 ; J19.47@2833.32,125.21 v1(2833.32,56.87) 2835.18,58.72 2849,58.72 2853.01,62.73 J19.49@2853.01,125.21 ; J18.16@2833.32,346.27 2833.32,406.18 2840.15,413.01 2853.01,413.01 ; J19.50@2853.01,350.8 2853.01,413.01 ; v1(2880.05,507.1) 2880,507.05 2880,440 2853.01,413.01
  Int5 (GND&PW) w30: v1@1092,663 1095.34,666.34 1095.34,672.78 1188.53,765.97 1309.27,765.97 1334.44,791.15 1362.23,791.15 1446.8,875.71 ; v1@1237,1435 1237,1344.18 1256.98,1324.19 v3(1256.98,1233.37) ; v3@1334,1235 1383.79,1284.79 1383.79,1305.2 1439.91,1361.33 v1(1439.91,1381.72) ; v1@1476,713 1446.8,742.2 1446.8,875.71 ; v1(1481.07,926.08) 1481.07,909.98 1446.8,875.71 ; v1@1483,927 1412.74,997.26 v1(1412.74,1220.58) 1428.36,1204.96 1441.48,1204.96 1459.05,1187.39 1459.05,1172.95 1471.64,1160.36 v1(1543.66,1160.36) ; v1@1543.66,1160 1629.21,1160 1736.26,1267.05 1826.47,1267.05 1842.21,1282.79 ; v1@1749,1844 1785.98,1807.02 1840.58,1807.02 1861.67,1785.93 ; v1(1793.79,1641.52) 1793.79,1715.8 1811.37,1733.37 1843.6,1733.37 1861.67,1751.44 1861.67,1785.93 ; v1@1812,915 1875.49,978.49 1875.49,1089.29 ; 1875,1255 1847.21,1282.79 1842.21,1282.79 ; 1875.49,1255 1875.49,1089.29 ; v1(1885.25,1490.85) 1885.25,1468.49 1902.22,1451.52 1902.22,1422.06 1874.16,1393.99 1874.16,1314.74 v1(1866.76,1307.34) 1842.21,1282.79 ; v1(1909,1937) 1914.16,1931.84 1914.16,1838.43 1911.76,1836.03 ; v1(1957.28,888.07) 2028,817.35 2030.64,817.35 2068.52,855.23 2068.52,1002.35 1981.58,1089.29 1875.49,1089.29 ; v1(2450,1805.18) 2450,1618.64 2513.26,1555.38 2513.26,1145.15 2880.05,778.36 v1(2880.05,507.1) 2833.32,460.37 v1(2833.32,56.87) ; 2465,1602 2463.84,1600.84 2354.53,1600.84 2303.79,1651.57 v1(2296.82,1651.57) 2295.57,1650.33 2269.29,1650.33 2158.62,1761 2088,1761 2084.78,1764.22 2020.78,1764.22 1948.97,1836.03 1911.76,1836.03 ; 1861.67,1785.93 1911.76,1836.03
  Int5 (GND&PW) w50: J13.2@889.64,2056.02 889.64,1878.92 1060.8,1707.75 1069.19,1707.75 1236,1540.94 v1@1236,1507
  Int6 (GND&PW) w40: J13.2@889.64,2056.02 969.29,1976.37 991.67,1976.37 1021.6,1946.44 1234.99,1946.44 1292.89,1888.53 1359.92,1888.53 1427.24,1955.84 1457.15,1955.84 1462.15,1960.84 1518.19,1960.84 1620.31,1858.71 1733.56,1858.71 v1(1747.68,1844.6)
  Bottom Layer w8: C66.1@1047.21,747.38 1047.21,706.85 v1(1094.06,660) ; v1(1237.92,1435.85) 1239.89,1433.89 U32.5@1293.04,1433.89 ; U17.7@1366.9,803.34 1367.82,802.41 1367.82,769.24 1423.52,713.55 v1(1485.4,713.55) 1488.45,713.55 C67.1@1490,712 ; U12.5@1498.39,1159.37 1498.88,1159.86 1543.17,1159.86 v1(1543.66,1160.36) ; v1(1695.24,1631.68) 1714.92,1651.36 1765.11,1651.36 1770.96,1657.21 v1(1770.96,1664.36) ; U9.14@1738.67,1631.68 1783.95,1631.68 v1(1793.79,1641.52) ; U21.2@1995.44,787.01 2010.79,787.01 2032.35,808.57 v1(2032.35,810.51) ; U39.8@2201.31,1499.83 2201.31,1539.82 2201.16,1539.98 2201.16,1574.24 2212.13,1585.21 v1(2212.13,1588.37)
  Bottom Layer w10: v1@1412.74,1218.74 1412.74,1199.66 C68.1@1418.4,1194 ; C29.1@1838.55,1283.12 1842.49,1283.12 v1@1864.36,1305 ; U11.8@1873.59,1378.2 1921.2,1378.2 1928,1385 1928,1419.76 1885.25,1462.52 v1(1885.25,1490.85) ; v1@1906,1938 1909,1935 1909,1884.38 1925.79,1867.59 1926.39,1867.59 1940.98,1853 U13.2@1950.82,1853
  Bottom Layer w50: J13.2@889.64,2056.02 892.5,2058.89 988.79,2058.89 994.08,2064.17 C123.2@994.08,2075
  other v1: 1808,912 1237.92,1435.85 1215.29,1473.26 1215.29,1473.26 1260.56,1473.26 1260.56,1473.26 1237.92,1510.66 1770.96,1618.69 1770.96,1618.69 1816.63,1618.69 1816.63,1618.69 1793.79,1641.52 1770.96,1664.36 1816.63,1664.36 1816.63,1664.36 994.64,2075
  other v3: 1296.35,1194 1296.35,1233.37 1296.35,1272.74
VDD_12VN_0: C121.2 C122.2 C125.2 C126.2 C127.2 C135.2 C136.2 J12.2 J13.1 R159.2 R160.2 R162.1 U42.5 U42.6 U42.16 U42.17 U42.24 U42.27 U42.28 U42.29 | length 1164.6
  Top Layer w8: R159.2@744.88,2493.86 v1(744.88,2541.89) ; J12.2@806.71,2804 799.06,2796.35 799.06,2666.28 v1(791.4,2658.62) 834.16,2658.62 849,2673.47 v1(849,2674.45) ; v2(942.79,2414.29) v2(942.79,2458.58) U42.24@942.79,2495
  Top Layer w12: v1(770,2294.8) 789,2313.8 795.5,2313.8 814.57,2332.86 814.57,2345.03 833.63,2364.1 U42.5@872.91,2364.1 873.61,2363.39 U42.29@930.69,2363.39 ; v1(840,2186.16) 893.26,2186.16 C125.2@897.75,2181.67 ; U42.6@872.91,2338.5 910.31,2338.5 930.98,2359.17 U42.29@942.79,2359.17 947.01,2363.39 1011.97,2363.39 U42.17@1012.67,2364.1 1037.11,2364.1 1044.14,2357.07 1044.14,2339.02 1043.63,2338.5 ; U42.29@938.85,2355.24 v2(942.79,2351.3) ; U42.16@1012.67,2338.5 1043.63,2338.5 ; 1046.85,2341.73 1061.52,2327.06 ; v1(1101.23,2293.58) 1094.73,2293.58 1067.7,2320.61 1061.52,2320.61 1043.63,2338.5
  Top Layer w20: J13.1@789.64,2056.02 812.12,2078.5 812.12,2085.22 897.75,2170.85 C125.2@897.75,2181.67
  Bottom Layer w12: v1(1044.14,2187.14) 1089.85,2187.14 1095.33,2181.67 v1(1097.41,2181.67)
  other v2: 923.5,2382.8 962.08,2382.8
VDD_12VP: C21.2 C22.2 C23.2 C24.2 C25.2 C26.2 C42.2 C59.2 C60.2 C61.2 C62.2 C103.1 C104.1 C105.1 C106.1 C149.1 J10.2 J18.18 J18.19 J19.51 J19.52 J19.53 J19.54 U8.8 U9.6 U9.7 U10.8 U11.5 U12.9 U13.5 U14.8 U15.6 U15.7 U16.4 U17.4 U18.11 U19.8 U20.4 U21.11 U22.11 U24.13 U25.11 U27.45 U28.3 U30.8 U32.8 U33.8 U39.5 U41.18 U41.24 | length 10021.4
  Top Layer w6: v1(2219,1801) 2221.26,1803.26 2259.46,1803.26 U24.13@2261.38,1805.18 ; v1(2348.53,1409) 2348.76,1409.22 2348.76,1454.78 U25.11@2348.98,1455.01
  Top Layer w8: U27.45@1117.09,718.07 1117.09,672.25 1126.18,663.16 v1(1126.18,660) ; C62.2@1133.43,1478.68 C62.2@1134.25,1477.86 ; v1(1158,1377.36) 1134.25,1401.11 C62.2@1134.25,1477.86 ; v1(1173,1212) 1176.16,1212 1184.74,1220.58 U28.3@1218.6,1220.58 ; U33.8@1182.81,1473.26 1138.85,1473.26 C62.2@1134.25,1477.86 ; v1(1626.34,1100.14) 1649.42,1100.14 1672.56,1077 U14.8@1687,1077 ; U15.6@1848.91,1631.68 1903.67,1631.68 ; U15.7@1848.91,1651.36 1901.75,1651.36 1901.75,1633.6 1903.67,1631.68 ; 1919.32,1631.68 1903.67,1631.68 ; 1921.87,1629.87 C26.2@1934,1617.74 ; U22.11@1933.43,699.41 1933.43,669.58 v1(1957.01,646) ; 1947.24,1913.85 1965.68,1895.42 U20.4@1965.68,1888.53
  Top Layer w10: v1(1770.46,2194.19) 1772.15,2192.5 1785.76,2192.5 1792.58,2185.69 v1(1792.58,2181.75) ; U16.4@1891.9,1867.39 1919.39,1867.39 1943,1891 v1@1943,1920.94 ; U18.11@2044.61,1391.98 2091.78,1391.98 2099.81,1383.95 2114.63,1383.95 2144.75,1353.84 v1(2144.75,1299) ; J19.51@2872.69,125.21 2872.69,62.73 2876.7,58.72 2890.52,58.72 v1(2892.38,56.87) J19.53@2892.38,125.21 ; J19.52@2872.69,350.8 J19.52@2872.69,350.8 2872.74,409.14 2878.59,415 2905,415 ; J19.54@2892.38,350.8 2892.87,351.29 2892.87,402.87 2905,415 ; v1(2935,507.1) 2935,445 2905,415
  Top Layer w12: v1(1748.8,2181.75) 1748.8,2185.69 1754.61,2191.5 1765.68,2191.5 1768.38,2194.19 v1(1770.46,2194.19) ; J10.2@1769.3,2285.55 1769.3,2273.27 1799.33,2243.25 U41.18@1869.22,2243.25 ; U41.24@1984.38,2182.22 1984.38,2175.52 1993.05,2166.85 1993.05,2162.25 v1(2020.79,2134.51)
  Int5 (GND&PW) w30: 1612.22,1101.84 1590,1079.62 1590,966.56 v1(1693.66,862.89) ; v1(1648.95,1530.19) 1853.27,1530.19 1896.71,1573.63 1896.71,1576.51 1935.3,1615.1 v1(1935.3,1620.51) ; v1@1692,862.89 1692,787 1773.85,705.15 1850.59,705.15 1853.09,707.65 1878.64,707.65 1881.14,705.15 1906.7,705.15 1907.86,704 1939.44,704 1957.01,686.42 v1(1957.01,646) ; 1720.43,758.57 1763.85,802 v1@1818,802 ; v1(2892.38,56.87) 2892.38,432.38 2935,475 v1(2935,507.1)
  Int6 (GND&PW) w30: v1@1128,662 1219.84,753.84 1297,753.84 1334.3,791.15 1353.06,791.15 1407.59,845.68 1407.59,895.05 1406,896.63 v1(1406,946) 1457.37,946 1468.29,956.92 1519.76,956.92 1567.72,908.96 1645.04,908.96 v1@1693,861 ; v1(1158,1377.36) 1147.16,1366.52 1147.16,1237.23 1165.22,1219.16 ; v1@1174,1213 1203,1213 1203,1225.79 1300.48,1323.27 1427.41,1323.27 1490.42,1260.26 1490.42,1234.86 1538.26,1234.86 1626.34,1146.78 ; v1(1626.34,1100.14) 1626.34,1146.78 ; v1@1650,1532 1624.21,1506.21 1624.21,1365.17 v1@1691.19,1298.19 ; v1@1692,1299 1626.34,1233.34 1626.34,1146.78 ; v1(1935.3,1620.51) 1905.19,1620.51 1849.16,1676.54 1849.16,1738.93 1885.76,1775.53 1885.76,1843.43 1952,1909.68 ; v1(2059.79,1088.68) 2059.79,1024.21 2267.46,816.54 2825.56,816.54 2935,707.1 v1(2935,507.1)
  Int6 (GND&PW) w50: v1(1792.58,2181.75) 1816.45,2157.88 1882,2157.88 ; 1882,2157 1998.3,2157 v1(2020.79,2134.51) 2052.78,2166.5 2243.05,2166.5 2273.85,2135.7 2273.85,2054.62 ; 1952,1909.68 1979.32,1882.35 2047.35,1882.35 2147.96,1982.96 ; 2195.69,2030.69 2151.5,1986.5 2259.84,1878.16 2259.84,1831.84 2230,1802 ; 2200.69,2030.69 2249.92,2030.69 2273.85,2054.62 ; 2273.85,2030.69 2273.85,2054.62
  Int7(Signal) w30: v1@2218,1800 2249.84,1768.16 2249.84,1677.22 2242.97,1670.35 2242.97,1579.41 2309.66,1512.71 2309.66,1447.87 v1(2348.53,1409)
  Bottom Layer w8: C59.2@1097.41,747.38 1097.41,743.44 1126.18,714.66 v1(1126.18,660) ; v1(1158,1377.36) 1157.94,1377.42 1157.94,1399.2 1146,1411.15 1146,1446.28 1168.01,1468.3 1170.76,1468.3 1175.72,1473.26 U32.8@1182.81,1473.26 ; v1(1173,1212) 1214.94,1212 C61.2@1215.65,1212.7 ; v1(1626.34,1100.14) 1626.42,1100.23 1671.53,1100.23 U12.9@1671.61,1100.32 ; v1(1812.9,799.83) 1813.19,799.83 1826.01,787.01 U21.11@1845.83,787.01 ; U9.7@1848.91,1631.68 1901.75,1631.68 ; U9.6@1848.91,1651.36 1895.49,1651.36 1900.18,1646.68 1900.18,1633.25 1901.75,1631.68 ; v1(1935.3,1620.51) 1931.36,1620.51 1920.19,1631.68 1901.75,1631.68 ; U39.5@2240.68,1673.06 2240.68,1710.17 2250.88,1720.36 C42.2@2250.88,1797.63
  Bottom Layer w10: v1(1406,946) 1406.19,945.81 1406.19,913.65 U17.4@1406.27,913.57 ; U11.5@2046.81,1338.83 2047.72,1337.93 2070.36,1337.93 2109.28,1299 v1(2144.75,1299) ; C42.2@2244.06,1790.82 C42.2@2250.88,1797.63
  Bottom Layer w12: C21.2@1670.04,810.51 1673.88,810.51 1679.69,816.32 1679.69,857.08 1685.5,862.89 C23.2@1689.33,862.89 v1(1693.66,862.89)
  Bottom Layer w20: C104.1@1699.79,2192.06 1700.38,2191.48 C103.1@1768.71,2191.48 ; U13.5@2053.18,1815.6 2129.04,1815.6 2195.44,1882 2229.7,1882 2250.88,1860.83 C42.2@2250.88,1797.63 ; v1(2219,1801) 2220.56,1799.44 C42.2@2249.07,1799.44
  Bottom Layer w50: C103.1@1769.3,2194.19 J10.2@1769.3,2285.55
  other v1: 1693.38,1296 1945.01,1925.57
VDD_12VP_0: C100.1 C101.1 C102.1 J9.2 J10.1 R148.2 U40.7 U40.8 U40.9 U40.10 U40.12 U40.13 U40.14 U40.15 U40.22 U40.30 | length 1125.9
  Top Layer w8: U40.22@1326.05,2295.41 1292.43,2295.41 1284.15,2303.69 1284.15,2406.27 1330,2452.13 J9.2@1330,2455.63 ; U40.7@1508.57,2185.73 U40.7@1508.13,2186.16 1508.13,2250.14 v2(1514.04,2256.04) 1508.13,2261.95 U40.15@1508.13,2325.92 1508.57,2326.36 v1(1545.54,2326.36) 1550.46,2321.44 U40.13@1550.46,2295.41 U40.12@1550.46,2275.73 ; U40.8@1550.46,2190.65 v1(1545.54,2185.73) 1619.31,2185.73 C101.1@1642.7,2209.12 ; U40.9@1550.46,2216.67 C101.1@1635.15,2216.67 ; U40.10@1550.46,2236.36 1615.46,2236.36 C101.1@1635.15,2216.67 ; C101.1@1653.53,2209.12 C101.1@1642.7,2209.12 ; C101.1@1635.15,2216.67 C101.1@1642.7,2209.12
  Int5 (GND&PW) w20: v1(1194.43,2161.18) 1520.99,2161.18 v1(1545.54,2185.73)
  other v1: 1654,2210 1653.53,2311.93
VDD_15VN: C132.2 C134.2 J6.3 J12.1 | length 180.9
  Bottom Layer w25: C134.2@1096.66,2812 1096.66,2813.62 1097.34,2814.31 C132.2@1169,2814.31 ; C132.2@1174.34,2792.69 1277.69,2792.69 J6.3@1280,2795
VDD_15VP: C107.1 C108.1 C109.1 C133.1 C135.1 C136.1 C138.1 C139.1 J5.1 J6.1 J7.1 J9.1 R147.2 R157.2 U40.3 U40.4 U40.18 U40.19 U42.3 U42.4 U42.18 U42.19 | length 2161.3
  Top Layer w12: R157.2@744.88,2448.03 744.88,2393.8 763.88,2374.8 v1(770,2374.8) ; C136.1@776.5,2374.8 C136.1@793.35,2391.65 ; C136.1@795,2390 795,2393.3 795.5,2393.8 798.8,2393.8 800.59,2395.59 820,2395.59 ; U42.4@872.91,2395.59 820,2395.59 ; U42.3@872.91,2421.18 822.88,2421.18 820,2418.3 820,2395.59 ; U42.18@1012.67,2395.59 1072.72,2395.59 1094.73,2373.58 v1(1101.23,2373.58) 1101.23,2414.15 1094.2,2421.18 U42.19@1012.67,2421.18 ; v1(1369.55,2066.61) 1420.61,2066.61 1446.09,2092.08 v1(1446.09,2093.26) ; U40.3@1399.87,2186.16 1399.87,2126.7 1413.16,2113.41 1427.4,2113.41 C138.1@1444.16,2096.65 1425.46,2115.35 U40.4@1425.46,2186.16 ; U40.19@1399.87,2325.92 1399.87,2417.97 1422.97,2417.97 C139.1@1425.46,2420.46 ; U40.18@1425.46,2325.92 C139.1@1425.46,2420.46 ; C139.1@1430,2425 C139.1@1425.46,2420.46
  Int6 (GND&PW) w50: J7.1@906.71,2956.69 1518.31,2956.69 J6.1@1680,2795
  Bottom Layer w25: C107.1@1620,2685.95 1625.37,2680.57 1625.37,2620.69 1626.06,2620 v1(1628.62,2620) v1(1628.62,2575) v1(1628.62,2525)
  Bottom Layer w50: C107.1@1620,2685.95 1620,2735 J6.1@1680,2795
  other v1: 1439.39,2442.3
VEE_LV_ext: C3.2 C4.2 C7.2 C8.2 C16.2 C17.2 C18.2 R9.2 R10.2 R20.2 R21.2 R213.2 U1.1 U1.6 U1.13 U2.1 U2.6 U2.13 U3.1 U3.6 U3.13 U4.1 U4.6 U4.13 U5.1 U5.4 U5.9 U6.1 U6.4 U6.9 U7.2 | length 4141.3
  Top Layer w12: v1(2658,2343.64) 2808.87,2343.64 2815.96,2350.73 2964.75,2350.73 2995.8,2319.68 2995.8,2301.53 3017.33,2280 U7.2@3051.18,2280
  Int6 (GND&PW) w20: v1(2662.84,2061) 2680,2061 2741,2122 ; v2(2786,1955) 2836.47,1955 2840,1955 ; 2836.47,2040 2859.17,2040 ; 2859.17,2032 3158.3,2032 v2(3191,2064.7)
  Int6 (GND&PW) w50: v1(2587.48,2409.48) 2653.32,2343.64 v1(2658,2343.64) 2701,2300.64 2701,2175.47 2836.47,2040 2836.47,1955 2836.47,1548.85 3046.96,1338.36
  Bottom Layer w8: U3.6@2853.04,1062.82 2853.04,1090.44 2900.22,1137.62 v2(2902.26,1137.62) 2904.29,1137.62 2951.47,1090.44 U3.1@2951.47,1062.82 ; v2(2859.17,1541.17) 2859.17,1550.87 U4.1@2859.17,1615.97 ; v2(2908.39,1541.17) 2910.42,1541.17 2957.6,1588.35 U4.6@2957.6,1615.97 ; U1.6@3163.26,1062.82 v2(3163.26,1137.62) ; U2.1@3163.65,1615.97 3163.65,1588.35 3210.83,1541.17 v2(3212.87,1541.17) ; v2(3212.47,1137.62) 3214.5,1137.62 3261.69,1090.44 U1.1@3261.69,1062.82 ; v2(3262.08,1541.17) U2.6@3262.08,1615.97
  Bottom Layer w10: R10.2@3100.81,1609.59 3100.81,1605.66 3107.62,1598.85 3111.56,1598.85 3125.1,1585.3 3158.81,1585.3 3163.65,1580.46 v2(3163.65,1541.17)
  Bottom Layer w20: R213.2@2610.5,2505 2610.5,2452.27 2623.44,2439.33 C16.2@2627.38,2439.33 ; v1(2662.84,2061) 2665.03,2063.19 2708.94,2063.19 U5.4@2710.75,2065 ; U5.1@2692.05,1915 U5.1@2710.75,1915 2795,1915 U5.9@2799,1919 ; R21.2@2779.54,1501.89 C4.2@2779.54,1550.87 2859.17,1550.87 2898.68,1550.87 v2(2908.39,1541.17) ; U3.13@2904.29,1137.62 v2(2951.47,1137.62) 2997.25,1137.62 C7.2@3027,1107.87 ; C7.2@3027,1103.94 C7.2@3027,1107.87 ; R20.2@3027,1153.38 C7.2@3027,1107.87 ; U6.4@3116,1958.4 3116,2016.63 3164.07,2064.7 v2(3191,2064.7) 3217.93,2064.7 3266,2016.63 U6.1@3266,1958.4 ; v2(3261.69,1137.62) 3269.55,1129.76 R9.2@3329,1129.76 C3.2@3329,1086.44 ; v2(3262.08,1541.17) 3285.29,1541.17 3317.81,1573.69 C8.2@3317.81,1577.62
  other v2: 2902.26,1096.28 3212.47,1096.28 2853.04,1137.62 2902.26,1178.96 3212.47,1178.96 2908.39,1499.83 3212.87,1499.83 2957.6,1541.17 2908.39,1582.51 3212.87,1582.51
VSENSE: R89.2 U18.10 U18.16 | length 856.5
  Top Layer w6: v1(1923.78,1480.19) 1923.78,1476.49 1928.51,1471.75 1928.51,1456.9 U18.16@1931.42,1453.99 ; U18.10@2044.61,1366.39 2046.25,1364.75 2104.36,1364.75 v1(2106,1363.11)
  Int2(Signal) w6: v1(1699.79,1734.43) 1714.57,1734.43 1765.8,1683.2 1824.43,1683.2 1835.47,1672.16 1835.47,1568.5 v1(1923.78,1480.19) ; v1(2106,1363.11) 2124.84,1381.95 2124.84,1461.35 v1(2106,1480.19)
  Int9(Signal) w6: v1(1923.78,1480.19) 1942.62,1499.04 1984.23,1499.04 2003.07,1480.19 v1(2106,1480.19)
  Bottom Layer w6: v1(1699.79,1734.43) 1699.79,1739.74 1724.26,1764.22 R89.2@1728.2,1764.22
Vsense_N_LV_Sh: J18.7 J19.30 R194.2 | length 281
  Top Layer w6: R194.2@2648.84,628.72 2648.84,439.19 2656.16,431.87 J19.30@2656.16,350.8
Vsense_P_LV_Sh: J18.8 J19.32 R193.2 | length 297.7
  Top Layer w6: J19.32@2675.84,350.8 2675.84,429.16 2665,440 2665,592.65 2688.32,615.97 2690.33,615.97 2699.14,624.78 R193.2@2699.14,628.72
pads on no net: D1.3 D2.3 D3.3 D4.3 FID1.1 FID2.1 FID3.1 FID4.1 FID5.1 FID6.1 H1.1 H2.1 H3.1 J8.1 J8.2 J8.4 J8.5 J8.7 J8.9 J8.11 J8.13 J8.15 J8.16 J8.17 J8.19 J8.21 J8.23 J8.25 J8.27 J8.29 J8.30 J8.31 J8.32 J8.33 J8.34 J8.35 J8.36 J8.37 J8.41 J8.43 J8.45 J8.47 J8.49 J8.50 J8.51 J8.52 J8.53 J8.55 J8.56 J8.57 J8.58 J8.59 J8.MH1 J8.MH2 J17.1 J17.2 J17.3 J17.4 J17.5 J17.6 J17.8 J17.9 J17.11 J17.12 J17.14 J17.21 J17.24 J17.26 J17.27 J17.28 J17.30 J17.31 J17.32 J17.33 J17.34 J17.36 J17.37 J17.39 J17.40 J17.41 J17.42 J17.43 J17.44 J17.45 J17.56 J17.57 J17.58 J17.59 J17.60 J17.61 J17.62 J17.64 J17.66 J17.68 J17.76 J17.78 J17.80 J17.82 J17.85 J17.86 J17.87 J17.88 J17.89 J17.90 J17.91 J17.92 J17.93 J17.94 J17.96 J17.99 J17.100 J17.101 J17.102 J17.103 J17.104 J17.105 J17.106 J17.107 J17.108 J17.109 J17.110 J17.113 J17.114 J17.115 J17.116 J17.117 J17.118 J17.119 J17.120 J17.181 J17.182 J17.185 J17.186 J19.1 J19.3 J19.7 J19.25 J19.27 J19.29 J19.31 J19.33 J19.35 J19.37 J19.39 J19.41 J19.43 J19.45 J19.MH1 J19.MH2 LBL1.0 RN2.4 RN2.5 RN2.6 RN2.7 RN3.4 RN6.4 RN7.4 SH-J1.0 SH-J2.0 SH-J3.0 SH-J4.0 SH-J5.0 SH-J6.0 U1.2 U1.5 U1.7 U1.8 U1.12 U2.2 U2.5 U2.7 U2.8 U2.12 U3.2 U3.5 U3.7 U3.8 U3.12 U4.2 U4.5 U4.7 U4.8 U4.12 U5.5 U5.8 U6.5 U6.8 U9.8 U9.13 U11.3 U15.8 U15.13 U16.5 U17.5 U18.5 U18.7 U18.13 U18.14 U21.10 U22.10 U23.22 U25.5 U25.7 U25.13 U25.14 U26.22 U27.1 U27.12 U27.13 U27.15 U27.24 U27.25 U27.29 U27.36 U27.37 U27.48 U28.13 U28.16 U32.1 U32.9 U32.10 U33.1 U33.9 U33.10 U39.3 U40.11 U40.26 U41.4 U41.19 U42.11 U42.26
